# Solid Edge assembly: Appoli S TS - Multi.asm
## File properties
Title: Appoli S TS - Multi
Author: petr.kostka
Keywords: ---
Template: Assembly Robe 03_24.asm
Last saved by: petr.kostka
Revision: 1302
Application: Solid Edge
Username: petr.kostka
Typ obsahu dokumentu: 1
Project Name: Appoli
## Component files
ek ramene.par
r Appoli.psm
roub Appoli M8.asm
r Calumma.psm
st Appoli S.par
13053496 Konektor Seetronic SAC3MPX LY IN.par
krytka Seetronic CNAC-MPX-LY IN.par
krytka IP65 DMX IN OUT.par
M3x12.par
ek Calumma.par
13032370 PCB RB3637-V2.1.A.1 2x DMX 5pin IP.asm
M3x10.par
sti Appoli S.par
11X40268 Rameno Appoli S.psm
Housing Appoli S.par
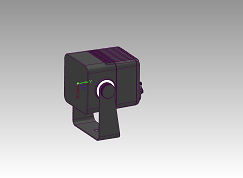
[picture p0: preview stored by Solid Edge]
